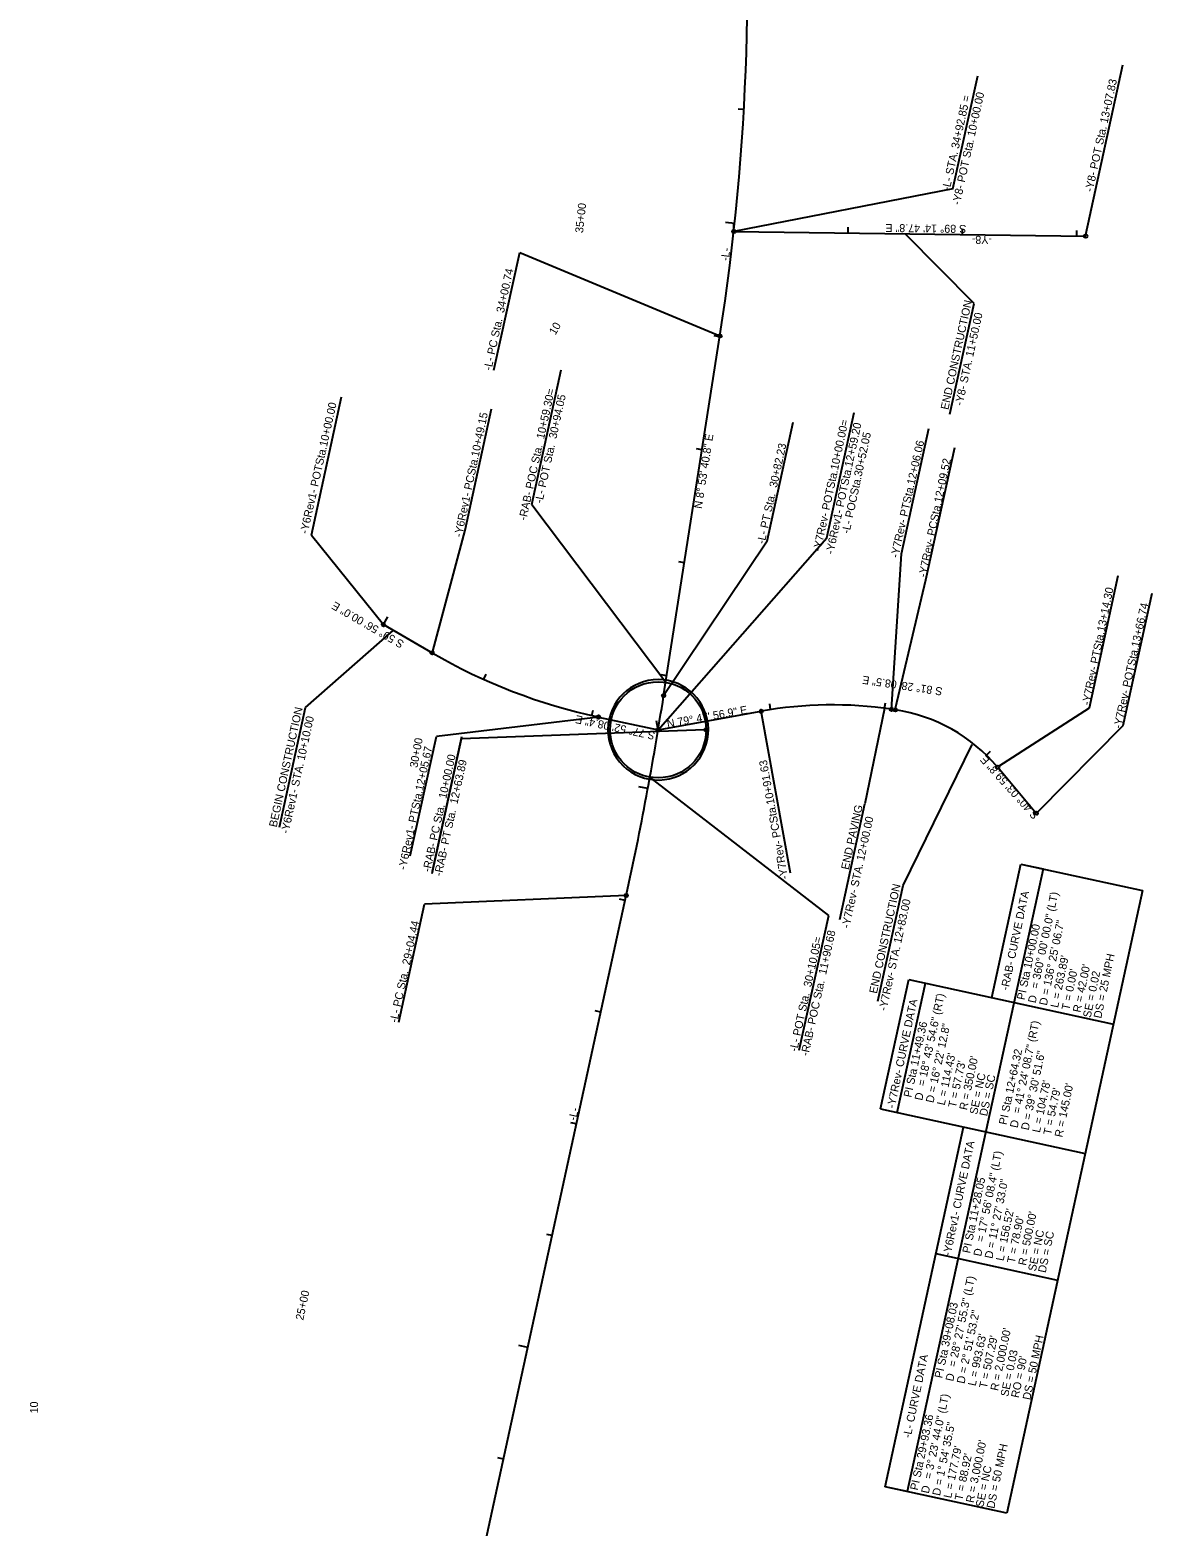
# Model space of a CAD drawing. Extents: x 1615712 to 1617175, y 899615 to 904865.
# Drawn here: x 1616072 to 1617054, y 900935 to 902243 of the extents above; entities that cross this region are included whole.
import ezdxf

# ---------------------------------------------------------------- set-up
doc = ezdxf.new("R2010")
doc.units = 0
for name, color, linetype in [('Prop Horizontal Alignment', 7, 'Continuous'), ('Prop Horizontal Alignment Curve and Spiral Data', 7, 'Continuous'), ('Prop Horizontal Alignment Direction Label', 7, 'Continuous'), ('Prop Horizontal Alignment Station Label', 7, 'Continuous'), ('Prop Horizontal Alignment Tick Label', 7, 'Continuous'), ('Prop Horizontal Alignment Tick Large', 7, 'Continuous'), ('Prop Horizontal Alignment Tick Small', 7, 'Continuous'), ('Prop Paint Stripe', 7, 'Continuous'), ('Scratch_Level_0', 7, 'Continuous')]:
    doc.layers.add(name, color=color, linetype=linetype)

msp = doc.modelspace()

# ---------------------------------------------------------------- linework, layer by layer
at = {"layer": 'Prop Horizontal Alignment'}
for p, q in [((1616626.3, 901660.8), (1616675.6, 901975.5)), ((1616626.3, 901660.8), (1616675.6, 901975.5)), ((1616381.2, 901723), (1616423.7, 901698.4)), ((1616569.2, 901642.2), (1616621.5, 901631)), ((1616621.5, 901631), (1616711.7, 901647.2)), ((1616621.5, 901631), (1616711.7, 901647.2)), ((1616825.6, 901648.9), (1616829.7, 901648.3)), ((1616825.6, 901648.9), (1616829, 901648.4)), ((1616918.5, 901598.3), (1616952.2, 901558.2)), ((1616188.3, 899625.3), (1616593.6, 901486.1)), ((1616188.3, 899625.3), (1616593.6, 901486.1))]:
    msp.add_line(p, q, dxfattribs=at)
msp.add_circle((1616621.5, 901631), 42, dxfattribs=at)
for centre, radius, start, end in [((1614699.6, 902284.7), 2000, 351.1053, 19.5707), ((1614699.6, 902284.7), 2000, 351.1053, 19.5707), ((1616674.2, 902131.1), 500, 239.9333, 257.869), ((1613662.4, 902124.6), 3000, 347.7098, 351.1053), ((1613662.4, 902124.6), 3000, 347.7098, 351.1053), ((1616773.7, 901302.8), 350, 81.469, 100.2009), ((1616773.7, 901302.8), 350, 81.469, 100.2009), ((1616807.5, 901505), 145, 40.0666, 81.469)]:
    msp.add_arc(centre, radius, start, end, dxfattribs=at)
at = {"layer": 'Prop Horizontal Alignment Curve and Spiral Data'}
for p, q in [((1616879.4, 902104), (1616687.7, 902066.8)), ((1616897.8, 902003.9), (1616837.7, 902064.8)), ((1616500.4, 902048.5), (1616675.6, 901975.5)), ((1616716.8, 901795.9), (1616626.3, 901660.8)), ((1616819.6, 901649.7), (1616802.4, 901566.2)), ((1616835.8, 901494.7), (1616896.3, 901618.2)), ((1616913.3, 901396.9), (1616938.8, 901513.6)), ((1616913.3, 901396.9), (1616938.8, 901513.6)), ((1616938.8, 901513.6), (1616958.3, 901509.4)), ((1616938.8, 901513.6), (1617045.3, 901490.4)), ((1616958.3, 901509.4), (1616839.4, 900964.8)), ((1616593.6, 901486.1), (1616417.1, 901478.5)), ((1617045.3, 901490.4), (1616926.4, 900945.8)), ((1616816, 901299.5), (1616840.7, 901412.7)), ((1616830.7, 901296.3), (1616855.4, 901409.5)), ((1616840.7, 901412.7), (1617019.8, 901373.6)), ((1616816, 901299.5), (1616995.1, 901260.4)), ((1616820, 900969), (1616888.6, 901283.6)), ((1616820, 900969), (1616888.6, 901283.6)), ((1616864.5, 901173), (1616970.9, 901149.8)), ((1616839.4, 900964.8), (1616820, 900969)), ((1616926.4, 900945.8), (1616820, 900969))]:
    msp.add_line(p, q, dxfattribs=at)
at = {"layer": 'Prop Horizontal Alignment Station Label'}
for p, q in [((1616995.5, 902064.2), (1617027.9, 902212.7)), ((1616879.4, 902104), (1616901, 902203)), ((1616687.7, 902066.8), (1616995.5, 902062.7)), ((1616477.9, 901945.6), (1616500.4, 902048.5)), ((1616876.7, 901907.2), (1616897.8, 902003.9)), ((1616626.3, 901660.8), (1616675.6, 901975.5)), ((1616626.3, 901660.8), (1616675.6, 901975.5)), ((1616626.3, 901660.8), (1616675.6, 901975.5)), ((1616318.2, 901801.1), (1616344.6, 901922.1)), ((1616452.7, 901805.6), (1616475.8, 901911.7)), ((1616769.1, 901799), (1616792.9, 901908.4)), ((1616716.8, 901795.9), (1616739.5, 901900.2)), ((1616834.4, 901785), (1616858.3, 901894.4)), ((1616855.6, 901762.3), (1616880.9, 901878)), ((1616511, 901828.1), (1616628.2, 901672.7)), ((1616318.2, 901801.1), (1616381.2, 901723)), ((1616424.5, 901699.7), (1616452.7, 901805.6)), ((1616621.5, 901631), (1616769.1, 901799)), ((1616825.6, 901648.9), (1616834.4, 901785)), ((1616829.2, 901649.9), (1616855.6, 901762.3)), ((1616998.7, 901650.3), (1617024, 901766)), ((1617028.3, 901634.7), (1617053.6, 901750.4)), ((1616381.2, 901723), (1616423.7, 901698.4)), ((1616569.2, 901642.2), (1616427.5, 901625.1)), ((1616569.2, 901642.2), (1616621.5, 901631)), ((1616737.2, 901505.7), (1616711.7, 901647.2)), ((1616919.6, 901599.3), (1616998.7, 901650.3)), ((1616662, 901631), (1616449.4, 901623.1)), ((1616953.4, 901559.1), (1617028.3, 901634.7)), ((1616404.7, 901520.7), (1616427.5, 901625.1)), ((1616770.7, 901468.6), (1616614.2, 901589.7)), ((1616780.3, 901465.2), (1616802.4, 901566.2)), ((1616813.8, 901393.7), (1616835.8, 901494.7)), ((1616394.6, 901375.4), (1616417.1, 901478.5)), ((1616770.7, 901468.6), (1616770.7, 901468.6))]:
    msp.add_line(p, q, dxfattribs=at)
for points in [[(1616511, 901828.1), (1616536.7, 901945.9)], [(1616290.2, 901545.8), (1616313, 901650.4), (1616389.8, 901717.9)], [(1616423.7, 901505.4), (1616449.4, 901623.1)], [(1616424.2, 901507.5), (1616449.9, 901625.3)], [(1616745, 901350.8), (1616770.7, 901468.6)]]:
    msp.add_lwpolyline(points, dxfattribs=at)
for centre in [(1616687.7, 902066.8), (1616995.5, 902062.7), (1616675.6, 901975.5), (1616381.2, 901723), (1616423.7, 901698.4), (1616626.3, 901660.8), (1616569.2, 901642.2), (1616711.7, 901647.2), (1616711.7, 901647.2), (1616825.6, 901648.9), (1616825.6, 901648.9), (1616829, 901648.4), (1616621.5, 901631), (1616621.5, 901631), (1616621.5, 901631), (1616663.5, 901631), (1616663.5, 901631), (1616918.5, 901598.3), (1616952.2, 901558.2), (1616593.6, 901486.1)]:
    msp.add_circle(centre, 1.5, dxfattribs=at)
for centre, radius, start, end in [((1614699.6, 902284.7), 2000, 351.1053, 19.5707), ((1614699.6, 902284.7), 2000, 351.1053, 19.5707), ((1614699.6, 902284.7), 2000, 351.1053, 19.5707), ((1616674.2, 902131.1), 500, 239.9333, 257.869), ((1616674.2, 902131.1), 500, 239.9333, 257.869), ((1616674.2, 902131.1), 500, 239.9333, 257.869), ((1616674.2, 902131.1), 500, 239.9333, 257.869), ((1616674.2, 902131.1), 500, 239.9333, 257.869), ((1616674.2, 902131.1), 500, 239.9333, 257.869), ((1613662.4, 902124.6), 3000, 347.7098, 351.1053), ((1613662.4, 902124.6), 3000, 347.7098, 351.1053), ((1613662.4, 902124.6), 3000, 347.7098, 351.1053), ((1616773.7, 901302.8), 350, 81.469, 100.2009), ((1616773.7, 901302.8), 350, 81.469, 100.2009), ((1616773.7, 901302.8), 350, 81.469, 100.2009), ((1616773.7, 901302.8), 350, 81.469, 100.2009), ((1616773.7, 901302.8), 350, 81.469, 100.2009)]:
    msp.add_arc(centre, radius, start, end, dxfattribs=at)
at = {"layer": 'Prop Horizontal Alignment Tick Large'}
for p, q in [((1616688.5, 902073.9), (1616680.5, 902074.7)), ((1616687.7, 902066.8), (1616687.8, 902074.8)), ((1616381.2, 901723), (1616385.2, 901729.9)), ((1616621.5, 901631), (1616620.1, 901638.9)), ((1616621.5, 901631), (1616620.1, 901638.9)), ((1616612.5, 901579.7), (1616604.6, 901581.2)), ((1616507.6, 901090.9), (1616499.7, 901092.6))]:
    msp.add_line(p, q, dxfattribs=at)
at = {"layer": 'Prop Horizontal Alignment Tick Small'}
for p, q in [((1616696.5, 902173.5), (1616691.5, 902173.8)), ((1616787.7, 902065.5), (1616787.8, 902070.5)), ((1616887.7, 902064.1), (1616887.8, 902069.1)), ((1616987.7, 902062.8), (1616987.7, 902067.8)), ((1616675.5, 901974.7), (1616670.5, 901975.5)), ((1616660, 901875.9), (1616655.1, 901876.7)), ((1616644.5, 901777.1), (1616639.6, 901777.9)), ((1616469, 901675.2), (1616471, 901679.7)), ((1616629.1, 901678.3), (1616624.1, 901679.1)), ((1616563.6, 901643.5), (1616564.7, 901648.3)), ((1616719.9, 901648.6), (1616719.2, 901653.6)), ((1616719.9, 901648.6), (1616719.2, 901653.6)), ((1616819.6, 901649.7), (1616820.3, 901654.7)), ((1616819.6, 901649.7), (1616820.3, 901654.7)), ((1616908.7, 901608.8), (1616912.2, 901612.4)), ((1616592.7, 901481.7), (1616587.8, 901482.8)), ((1616571.4, 901384), (1616566.5, 901385.1)), ((1616550.1, 901286.3), (1616545.2, 901287.4)), ((1616528.8, 901188.6), (1616524, 901189.7)), ((1616486.3, 900993.2), (1616481.4, 900994.2))]:
    msp.add_line(p, q, dxfattribs=at)
at = {"layer": 'Prop Paint Stripe'}
for start, end in [(260.1097, 167.869), (167.869, 260.1084)]:
    msp.add_arc((1616621.5, 901631), 43.9, start, end, dxfattribs=at)
at = {"layer": 'Scratch_Level_0'}
for p, q in [((1616626.3, 901660.8), (1616675.6, 901975.5)), ((1616626.3, 901660.8), (1616675.6, 901975.5)), ((1616188.3, 899625.3), (1616593.6, 901486.1))]:
    msp.add_line(p, q, dxfattribs=at)
msp.add_circle((1616621.5, 901631), 42, dxfattribs=at)
for centre, radius, start, end in [((1614699.6, 902284.7), 2000, 351.1053, 19.5707), ((1614699.6, 902284.7), 2000, 351.1053, 19.5707), ((1613662.4, 902124.6), 3000, 347.7098, 351.1053), ((1613662.4, 902124.6), 3000, 347.7098, 351.1053)]:
    msp.add_arc(centre, radius, start, end, dxfattribs=at)

# ---------------------------------------------------------------- texts
at = {"layer": 'Prop Horizontal Alignment Curve and Spiral Data'}
for s, rotation, p in [('-RAB- CURVE DATA', 78.1579, (1616927.9, 901402.7)), ('= 360%%d 00\' 00.0" (LT)', 78.1872, (1616954, 901404.2)), ('PI Sta 10+00.00', 78.1872, (1616942, 901394.3)), ('D = 136%%d 25\' 06.7"', 78.1872, (1616961.5, 901389.5)), ("L = 263.89'", 78.1872, (1616971.3, 901387.5)), ('DS = 25 MPH', 78.1579, (1617009.1, 901378.2)), ("T = 0.00'", 78.1872, (1616981.1, 901385.4)), ("R = 42.00'", 78.1872, (1616990.9, 901383.4)), ('SE = 0.02', 78.1579, (1616999.8, 901378.8)), ('-Y7Rev- CURVE DATA', 78.1579, (1616828.4, 901299.5)), ('= 18%%d 43\' 54.6" (RT)', 77.9276, (1616854.9, 901319)), ('D', 78.1872, (1616951.7, 901391.6)), ('PI Sta 11+49.36', 77.9276, (1616842.9, 901309.1)), ('D = 16%%d 22\' 12.8"', 77.9276, (1616862.3, 901304.3)), ('= 41%%d 24\' 08.7" (RT)', 78.1511, (1616938.2, 901295.1)), ("L = 114.43'", 77.9276, (1616872.1, 901302.2)), ("T = 57.73'", 77.9276, (1616881.9, 901300.1)), ("R = 350.00'", 77.9276, (1616891.6, 901298)), ('PI Sta 12+64.32', 78.1511, (1616926.2, 901285.1)), ('D = 39%%d 30\' 51.6"', 78.1511, (1616945.6, 901280.4)), ('SE = NC', 78.1579, (1616900.6, 901294.2)), ('DS = SC', 78.1579, (1616909.2, 901292.7)), ("L = 104.78'", 78.1511, (1616955.4, 901278.3)), ("T = 54.79'", 78.1511, (1616965.2, 901276.3)), ("R = 145.00'", 78.1511, (1616975, 901274.2)), ('D', 77.9276, (1616852.5, 901306.4)), ('D', 78.1511, (1616935.9, 901282.4)), ('-Y6Rev1- CURVE DATA', 78.1579, (1616877.3, 901170.4)), ('= 17%%d 56\' 08.4" (LT)', 78.487, (1616906.3, 901182.7)), ('PI Sta 11+28.05', 78.487, (1616894.3, 901172.8)), ('D = 11%%d 27\' 33.0"', 78.487, (1616913.8, 901168.1)), ("L = 156.52'", 78.487, (1616923.6, 901166.1)), ("T = 78.90'", 78.487, (1616933.4, 901164.1)), ("R = 500.00'", 78.487, (1616943.2, 901162.1)), ('SE = NC', 78.1579, (1616951.8, 901157)), ('DS = SC', 78.1579, (1616960.5, 901155.7)), ('D', 78.487, (1616904, 901170.1)), ('= 28%%d 27\' 55.3" (LT)', 78.1054, (1616882, 901073.4)), ('PI Sta 39+08.03', 78.1054, (1616870, 901063.5)), ('D = 2%%d 51\' 53.2"', 78.1054, (1616889.4, 901058.7)), ("R = 2,000.00'", 78.1054, (1616918.8, 901052.5)), ("L = 993.63'", 78.1054, (1616899.2, 901056.7)), ("T = 507.29'", 78.1054, (1616909, 901054.6)), ('DS = 50 MPH', 78.1579, (1616947, 901044.5)), ('-L- CURVE DATA', 78.1579, (1616842.4, 901011.2)), ('SE = 0.03', 78.1579, (1616927.7, 901047.4)), ("RO = 90'", 78.1579, (1616936.9, 901046.3)), ('D', 78.1054, (1616879.6, 901060.8)), ('= 3%%d 23\' 44.0" (LT)', 78.1579, (1616860.6, 900975.4)), ('PI Sta 29+93.36', 78.1579, (1616848.6, 900965.5)), ('D = 1%%d 54\' 35.5"', 78.1579, (1616868, 900960.7)), ("L = 177.79'", 78.1579, (1616877.8, 900958.6)), ("R = 3,000.00'", 78.1579, (1616897.4, 900954.5)), ('DS = 50 MPH', 78.1579, (1616915.5, 900949.5)), ("T = 88.92'", 78.1579, (1616887.6, 900956.6)), ('SE = NC', 78.1579, (1616905.9, 900950.7)), ('D', 78.1579, (1616858.2, 900962.7))]:
    msp.add_text(s, height=7, rotation=rotation, dxfattribs=at).set_placement(p)
at = {"layer": 'Prop Horizontal Alignment Direction Label'}
for s, rotation, p in [('S 89%%d 14\' 47.8" E', 179.2466, (1616891.1, 902072.5)), ('N 8%%d 53\' 40.8" E', 81.1053, (1616659.7, 901824)), ('S 59%%d 56\' 00.0" E', 149.9333, (1616399.9, 901708)), ('S 81%%d 28\' 08.5" E', 171.469, (1616870.6, 901667.8)), ('S 77%%d 52\' 08.4" E', 167.869, (1616619.2, 901629)), ('N 79%%d 47\' 56.9" E', 10.2009, (1616629.8, 901632.7)), ('S 40%%d 03\' 59.8" E', 132.0774, (1616955.1, 901556.7))]:
    msp.add_text(s, height=7, rotation=rotation, dxfattribs=at).set_placement(p)
at = {"layer": 'Prop Horizontal Alignment Station Label'}
for s, rotation, p in [('-Y8- POT Sta. 13+07.83', 77.6862, (1617001.5, 902101)), ('-L- STA. 34+92.85 =', 77.6862, (1616876.5, 902102.2)), ('-Y8- POT Sta. 10+00.00', 77.6862, (1616885.4, 902089.5)), ('-L- PC Sta.  34+00.74', 77.6862, (1616475.6, 901944.9)), ('END CONSTRUCTION', 77.6862, (1616875.3, 901910.5)), ('-Y8- STA. 11+50.00', 77.6862, (1616887.7, 901914)), ('-Y6Rev1- POTSta.10+00.00', 77.481, (1616314.9, 901802)), ('-RAB- POC Sta.  10+59.30=', 77.7141, (1616506.2, 901813.7)), ('-L- POT Sta.  30+94.05', 77.7141, (1616520.2, 901828.7)), ('-Y6Rev1- PCSta.10+49.15', 78.0794, (1616449.7, 901799.1)), ('-Y7Rev- POTSta.10+00.00=', 78.0083, (1616763.7, 901786.5)), ('-Y6Rev1- POTSta.12+59.20', 77.869, (1616774.8, 901784.1)), ('-L- POCSta.30+52.05', 77.869, (1616788.8, 901802.2)), ('-L- PT Sta.  30+82.23', 77.6862, (1616714.6, 901793.1)), ('-Y7Rev- PTSta.12+06.06', 77.4185, (1616831.5, 901780.9)), ('-Y7Rev- PCSta.12+09.52', 78.1721, (1616855.9, 901764)), ('-Y7Rev- PTSta.13+14.30', 78.5119, (1616999, 901652.1)), ('-Y7Rev- POTSta.13+66.74', 77.68, (1617026.5, 901631.6)), ('BEGIN CONSTRUCTION', 77.6862, (1616287.8, 901545.4)), ('-Y6Rev1- STA. 10+10.00', 77.6862, (1616298.2, 901539.7)), ('-Y6Rev1- PTSta.12+05.67', 77.869, (1616400.9, 901508.1)), ('-RAB- PC Sta.  10+00.00', 77.7141, (1616422.2, 901506.3)), ('-RAB- PT Sta.  12+63.89', 77.7141, (1616432.2, 901502.6)), ('-Y7Rev- PCSta.10+91.63', 100.2009, (1616735.3, 901500.8)), ('END PAVING', 77.6862, (1616788.2, 901508.2)), ('-Y7Rev- STA. 12+00.00', 77.6862, (1616788.7, 901457)), ('END CONSTRUCTION', 77.6862, (1616812.8, 901399.9)), ('-Y7Rev- STA. 12+83.00', 77.6862, (1616821.2, 901384.8)), ('-L- PC Sta.  29+04.44', 77.7103, (1616393.3, 901374.5)), ('-L- POT Sta.  30+10.05=', 77.7141, (1616743, 901349.1)), ('-RAB- POC Sta.  11+90.68', 77.7141, (1616752.9, 901345.3))]:
    msp.add_text(s, height=7, rotation=rotation, dxfattribs=at).set_placement(p)
at = {"layer": 'Prop Horizontal Alignment Tick Label'}
for s, rotation, p in [('35+00', 83.949, (1616555.8, 902065.2)), ('-Y8-', 180.0205, (1616913.5, 902063)), ('-L-', 82.6938, (1616683.2, 902040.8)), ('10', 59.9333, (1616531.6, 901975.8)), ('30+00', 79.5348, (1616410.9, 901597.4)), ('-L-', 77.7098, (1616549.7, 901288.7)), ('25+00', 77.7098, (1616311, 901114.2)), ('10', 90.894, (1616079.2, 901033.2))]:
    msp.add_text(s, height=7, rotation=rotation, dxfattribs=at).set_placement(p)

doc.saveas('drawing.dxf')
